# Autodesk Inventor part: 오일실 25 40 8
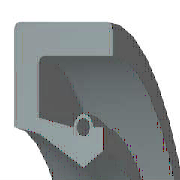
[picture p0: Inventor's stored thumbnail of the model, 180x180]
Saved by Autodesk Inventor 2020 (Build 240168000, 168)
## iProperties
Created: 2009-02
Part Number: 오일실 25 40 8
Material: 고무
Description: 오일-실
Document SubType Name: Modeling
Standard: KS B 2804
Designer: 진현석
Standards Organization: KS
Language: ko-KR
Size Designation: S - 25 40 8
Categories: <MemberInstance><Categories><Category DisplayName="샤프트 부품" InternalName="7f7aeb1f-a693-4053-b835-cee3144e0d98" Mnemonic="SHFT"><Category DisplayName="실링" Intern
Density: 0.93 g/cm^3
Appearance: 고무 - 검은색 - 버전 1.1
IsCustomPart: 1
Author: 진현석
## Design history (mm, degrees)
revolve "본체" stored, may be unused: angle "d17" = 90 deg
revolve "스프링1" stored, may be unused: angle "d18" = 90 deg
body "Solid1"
sketch "스케치1"
  geometry: L1 (0, 20)-(8, 20); L2 (8, 20)-(8, 18.75); L3 (8, 18.75)-(1.75, 18.75); L4 (0, 20)-(0, 14.6); L5 (0, 14.6)-(1.75, 14.25); L6 (1.75, 14.25)-(4.9, 12.5); L7 (4.9, 12.5)-(0, 12.5); L8 (6.3, 13.375)-(6.3, 14.6); L9 (0, 0)-(9.586, 0) reference; L10 (4.9, 12.5)-(6.3, 13.375); L11 (0, 18)-(0, -3) reference; L12 (-1.917, 0)-(11.503, 0) reference; L13 (4.2, 14.6)-(1.75, 15.09); L14 (1.75, 15.09)-(1.75, 18.75); L15 (6.3, 14.6)-(5.6, 14.6); C1 r 0.455 at (4.9, 14.6); A1 r 0.7 centre (4.9, 14.6) between (5.6, 14.6) and (4.2, 14.6)
  constraints: 26 end point, 5 horizontal alignment, 4 perpendicular, 2 centre point, 2 collinear, 2 horizontal, 2 parallel, 2 point on circle, 2 point on line, 2 vertical alignment, 1 coincident
  dimensions: "d0" = 40 diameter of L1 L9 (= SD2); "d1" = 26.75 diameter of L8.start L9 (= ABDM); "d2" = 1.25 distance of L1.end L2.end (computed from SD); "d3" = 0.91 diameter of C1 (= SPDI); "d4" = 1.4 diameter of A1 (= SPDA); "d5" = 25 diameter of L6.end L9 (= NND); "d6" = 28.5 diameter of L5.end L9 (= TKDM); "d7" = 29.2 diameter of L4.end L9 (= HLDM); "d8" = 4.9 distance from line of C1.centre L4 (= SPDST); "d9" = 6.3 distance between parallel lines of L8 L4 (= SDI); "d10" = 8 distance between parallel lines of L2 L4 (= SWDT); "d12" = 1.75 distance between parallel lines of L14 L4 (= SD)
fillet "모깎기1" dims "d11" = 0.3 (= RR)
other parameters: "SD2" = 40 [user parameter; used in 1 equation term], "SWDT" = 8 [user parameter; used in 1 equation term], "RR" = 0.3 [user parameter; used in 1 equation term], "SD" = 1.75 [user parameter; used in 2 equation terms], "NND" = 25 [user parameter; used in 1 equation term], "SPDA" = 1.4 [user parameter; used in 1 equation term], "SPDI" = 0.91 [user parameter; used in 1 equation term], "TKDM" = 28.5 [user parameter; used in 1 equation term], "HLDM" = 29.2 [user parameter; used in 1 equation term], "ABDM" = 26.75 [user parameter; used in 1 equation term], "SDI" = 6.3 [user parameter; used in 1 equation term], "SPDST" = 4.9 [user parameter; used in 1 equation term], "d13" = 0, "d14" = 0, "d15" = 0, "LAB" = 0.35 [user parameter]
